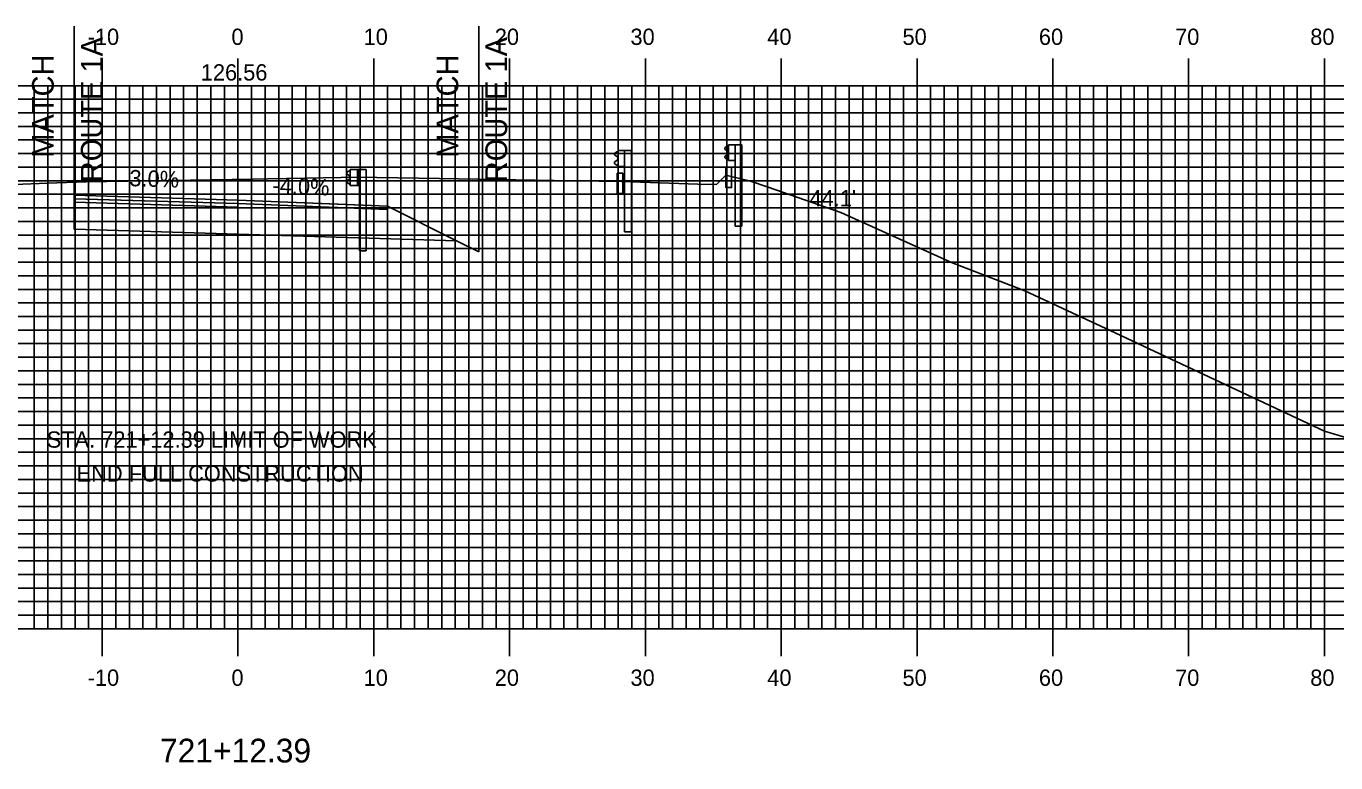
# Model space of a CAD drawing. Extents: x 858445 to 858788, y 364366 to 364586.
# Drawn here: x 858595.3 to 858691.7, y 364433.9 to 364488.2 of the extents above; entities that cross this region are included whole.
import ezdxf

# ---------------------------------------------------------------- set-up
doc = ezdxf.new("R2010")
doc.units = 0
for name, color, linetype in [('ANNOTATION', 7, 'Continuous'), ('D_Guardrail_Beam_Lt', 7, 'Continuous'), ('D_Roadway_Centerline_Text', 7, 'Continuous'), ('D_Roadway_Edge_Shoulder', 7, 'Continuous'), ('D_Roadway_Edge_TW', 7, 'Continuous'), ('D_Roadway_Pavement', 7, 'Continuous'), ('D_Roadway_SlopeLines', 7, 'Continuous'), ('D_Roadway_SubGrade', 7, 'Continuous'), ('D_Text_Standard', 7, 'Continuous'), ('H_V ANNOTATION', 7, 'Continuous'), ('M_Roadway_Centerline', 7, 'Continuous'), ('MAJOR', 7, 'Continuous'), ('MINOR', 7, 'Continuous'), ('S_Curb_Type_1', 7, 'Continuous'), ('S_Guardrail_Beam', 7, 'Continuous'), ('S_Roadway_Centerline', 7, 'Continuous')]:
    doc.layers.add(name, color=color, linetype=linetype)

msp = doc.modelspace()

# ---------------------------------------------------------------- linework, layer by layer
at = {"layer": 'D_Guardrail_Beam_Lt'}
for p, q in [((858619.056, 364477.508), (858618.912, 364477.408)), ((858618.912, 364477.265), (858619.107, 364477.128)), ((858619.107, 364476.929), (858618.912, 364476.793)), ((858619.146, 364477.529), (858619.071, 364477.514)), ((858619.141, 364477.064), (858619.141, 364476.994)), ((858619.146, 364477.612), (858619.833, 364477.612)), ((858619.146, 364476.446), (858619.146, 364477.612)), ((858619.666, 364477.612), (858619.666, 364476.446)), ((858619.771, 364477.612), (858619.771, 364476.446)), ((858619.833, 364477.612), (858620.304, 364477.612)), ((858619.833, 364477.612), (858619.833, 364476.446)), ((858620.304, 364477.612), (858620.304, 364471.612)), ((858618.912, 364476.65), (858619.056, 364476.55)), ((858619.071, 364476.543), (858619.146, 364476.529)), ((858619.833, 364476.446), (858619.146, 364476.446)), ((858619.812, 364471.612), (858619.812, 364476.446)), ((858619.812, 364471.612), (858620.304, 364471.612))]:
    msp.add_line(p, q, dxfattribs=at)
for centre, major_axis, start_param, end_param in [((858618.962, 364477.336), (-0.0877, 0), 5.323254, 7.243116), ((858618.962, 364476.722), (-0.0877, 0), 5.323254, 7.243116), ((858619.079, 364477.474), (-0.0417, 0), 4.907132, 5.323254), ((858619.062, 364477.064), (0.0789, 0), 0, 0.959931), ((858619.062, 364476.994), (0.0789, 0), 5.323254, 6.283185), ((858619.079, 364476.584), (-0.0417, 0), 0.959931, 1.376053)]:
    msp.add_ellipse(centre, major_axis=major_axis, ratio=0.995501, start_param=start_param, end_param=end_param, dxfattribs=at)
at = {"layer": 'D_Roadway_Edge_Shoulder'}
for points in [[(858610.875, 364475.349), (858621.875, 364474.909), (858621.875, 364474.659), (858610.875, 364475.099)], [(858610.875, 364475.349), (858618.875, 364475.029), (858618.875, 364475.029), (858621.875, 364474.909), (858621.875, 364474.659), (858610.875, 364475.099)]]:
    msp.add_lwpolyline(points, close=True, dxfattribs=at)
at = {"layer": 'D_Roadway_Edge_TW'}
for points in [[(858598.817, 364475.711), (858610.875, 364475.349), (858610.875, 364475.099), (858598.817, 364475.461)], [(858598.817, 364475.711), (858610.875, 364475.349), (858610.875, 364475.099), (858598.817, 364475.461)], [(858598.817, 364475.711), (858610.875, 364475.349), (858610.875, 364475.099), (858598.817, 364475.461)], [(858598.817, 364475.711), (858598.817, 364475.711), (858598.817, 364475.461), (858598.817, 364475.461)]]:
    msp.add_lwpolyline(points, close=True, dxfattribs=at)
at = {"layer": 'D_Roadway_Pavement'}
for points in [[(858598.817, 364475.461), (858598.817, 364475.461), (858598.817, 364475.211), (858598.817, 364475.211)], [(858598.839, 364475.46), (858610.875, 364475.099), (858610.875, 364474.849), (858598.839, 364475.21)]]:
    msp.add_lwpolyline(points, close=True, dxfattribs=at)
at = {"layer": 'D_Roadway_SlopeLines'}
msp.add_line((858626.96, 364472.366), (858628.602, 364471.545), dxfattribs=at)
at = {"layer": 'D_Roadway_SubGrade'}
for p, q in [((858598.817, 364488.168), (858598.817, 364473.211)), ((858628.602, 364488.168), (858628.602, 364473.211)), ((858628.602, 364473.211), (858628.602, 364471.545))]:
    msp.add_line(p, q, dxfattribs=at)
for points in [[(858598.817, 364475.211), (858598.817, 364475.211), (858598.817, 364473.211), (858598.817, 364473.211)], [(858598.839, 364475.21), (858610.875, 364474.849), (858610.875, 364472.849), (858598.839, 364473.21)], [(858610.875, 364474.849), (858610.875, 364475.099), (858621.875, 364474.659), (858621.875, 364474.909), (858626.96, 364472.366), (858610.875, 364472.849)]]:
    msp.add_lwpolyline(points, close=True, dxfattribs=at)
at = {"layer": 'MAJOR'}
for p, q in [((858600.875, 364485.791), (858600.875, 364483.787)), ((858610.875, 364485.791), (858610.875, 364483.787)), ((858620.875, 364485.791), (858620.875, 364483.787)), ((858630.875, 364485.791), (858630.875, 364483.787)), ((858640.875, 364485.791), (858640.875, 364483.787)), ((858650.875, 364485.791), (858650.875, 364483.787)), ((858660.875, 364485.791), (858660.875, 364483.787)), ((858670.875, 364485.791), (858670.875, 364483.787)), ((858680.875, 364485.791), (858680.875, 364483.787)), ((858690.875, 364485.791), (858690.875, 364483.787)), ((858470.875, 364483.787), (858750.875, 364483.787)), ((858470.875, 364483.787), (858750.875, 364483.787)), ((858600.875, 364443.787), (858600.875, 364483.787)), ((858610.875, 364443.787), (858610.875, 364483.787)), ((858620.875, 364443.787), (858620.875, 364483.787)), ((858630.875, 364443.787), (858630.875, 364483.787)), ((858640.875, 364443.787), (858640.875, 364483.787)), ((858650.875, 364443.787), (858650.875, 364483.787)), ((858660.875, 364443.787), (858660.875, 364483.787)), ((858670.875, 364443.787), (858670.875, 364483.787)), ((858680.875, 364443.787), (858680.875, 364483.787)), ((858690.875, 364443.787), (858690.875, 364483.787)), ((858470.875, 364478.787), (858750.875, 364478.787)), ((858470.875, 364473.787), (858750.875, 364473.787)), ((858470.875, 364468.787), (858750.875, 364468.787)), ((858470.875, 364463.787), (858750.875, 364463.787)), ((858470.875, 364458.787), (858750.875, 364458.787)), ((858470.875, 364453.787), (858750.875, 364453.787)), ((858470.875, 364448.787), (858750.875, 364448.787)), ((858470.875, 364443.787), (858750.875, 364443.787)), ((858470.875, 364443.787), (858750.875, 364443.787)), ((858600.875, 364441.783), (858600.875, 364443.787)), ((858610.875, 364441.783), (858610.875, 364443.787)), ((858620.875, 364441.783), (858620.875, 364443.787)), ((858630.875, 364441.783), (858630.875, 364443.787)), ((858640.875, 364441.783), (858640.875, 364443.787)), ((858650.875, 364441.783), (858650.875, 364443.787)), ((858660.875, 364441.783), (858660.875, 364443.787)), ((858670.875, 364441.783), (858670.875, 364443.787)), ((858680.875, 364441.783), (858680.875, 364443.787)), ((858690.875, 364441.783), (858690.875, 364443.787))]:
    msp.add_line(p, q, dxfattribs=at)
at = {"layer": 'MINOR'}
for p, q in [((858595.875, 364443.787), (858595.875, 364483.787)), ((858596.875, 364443.787), (858596.875, 364483.787)), ((858597.875, 364443.787), (858597.875, 364483.787)), ((858598.875, 364443.787), (858598.875, 364483.787)), ((858599.875, 364443.787), (858599.875, 364483.787)), ((858601.875, 364443.787), (858601.875, 364483.787)), ((858602.875, 364443.787), (858602.875, 364483.787)), ((858603.875, 364443.787), (858603.875, 364483.787)), ((858604.875, 364443.787), (858604.875, 364483.787)), ((858605.875, 364443.787), (858605.875, 364483.787)), ((858606.875, 364443.787), (858606.875, 364483.787)), ((858607.875, 364443.787), (858607.875, 364483.787)), ((858608.875, 364443.787), (858608.875, 364483.787)), ((858609.875, 364443.787), (858609.875, 364483.787)), ((858611.875, 364443.787), (858611.875, 364483.787)), ((858612.875, 364443.787), (858612.875, 364483.787)), ((858613.875, 364443.787), (858613.875, 364483.787)), ((858614.875, 364443.787), (858614.875, 364483.787)), ((858615.875, 364443.787), (858615.875, 364483.787)), ((858616.875, 364443.787), (858616.875, 364483.787)), ((858617.875, 364443.787), (858617.875, 364483.787)), ((858618.875, 364443.787), (858618.875, 364483.787)), ((858619.875, 364443.787), (858619.875, 364483.787)), ((858621.875, 364443.787), (858621.875, 364483.787)), ((858622.875, 364443.787), (858622.875, 364483.787)), ((858623.875, 364443.787), (858623.875, 364483.787)), ((858624.875, 364443.787), (858624.875, 364483.787)), ((858625.875, 364443.787), (858625.875, 364483.787)), ((858626.875, 364443.787), (858626.875, 364483.787)), ((858627.875, 364443.787), (858627.875, 364483.787)), ((858628.875, 364443.787), (858628.875, 364483.787)), ((858629.875, 364443.787), (858629.875, 364483.787)), ((858631.875, 364443.787), (858631.875, 364483.787)), ((858632.875, 364443.787), (858632.875, 364483.787)), ((858633.875, 364443.787), (858633.875, 364483.787)), ((858634.875, 364443.787), (858634.875, 364483.787)), ((858635.875, 364443.787), (858635.875, 364483.787)), ((858636.875, 364443.787), (858636.875, 364483.787)), ((858637.875, 364443.787), (858637.875, 364483.787)), ((858638.875, 364443.787), (858638.875, 364483.787)), ((858639.875, 364443.787), (858639.875, 364483.787)), ((858641.875, 364443.787), (858641.875, 364483.787)), ((858642.875, 364443.787), (858642.875, 364483.787)), ((858643.875, 364443.787), (858643.875, 364483.787)), ((858644.875, 364443.787), (858644.875, 364483.787)), ((858645.875, 364443.787), (858645.875, 364483.787)), ((858646.875, 364443.787), (858646.875, 364483.787)), ((858647.875, 364443.787), (858647.875, 364483.787)), ((858648.875, 364443.787), (858648.875, 364483.787)), ((858649.875, 364443.787), (858649.875, 364483.787)), ((858651.875, 364443.787), (858651.875, 364483.787)), ((858652.875, 364443.787), (858652.875, 364483.787)), ((858653.875, 364443.787), (858653.875, 364483.787)), ((858654.875, 364443.787), (858654.875, 364483.787)), ((858655.875, 364443.787), (858655.875, 364483.787)), ((858656.875, 364443.787), (858656.875, 364483.787)), ((858657.875, 364443.787), (858657.875, 364483.787)), ((858658.875, 364443.787), (858658.875, 364483.787)), ((858659.875, 364443.787), (858659.875, 364483.787)), ((858661.875, 364443.787), (858661.875, 364483.787)), ((858662.875, 364443.787), (858662.875, 364483.787)), ((858663.875, 364443.787), (858663.875, 364483.787)), ((858664.875, 364443.787), (858664.875, 364483.787)), ((858665.875, 364443.787), (858665.875, 364483.787)), ((858666.875, 364443.787), (858666.875, 364483.787)), ((858667.875, 364443.787), (858667.875, 364483.787)), ((858668.875, 364443.787), (858668.875, 364483.787)), ((858669.875, 364443.787), (858669.875, 364483.787)), ((858671.875, 364443.787), (858671.875, 364483.787)), ((858672.875, 364443.787), (858672.875, 364483.787)), ((858673.875, 364443.787), (858673.875, 364483.787)), ((858674.875, 364443.787), (858674.875, 364483.787)), ((858675.875, 364443.787), (858675.875, 364483.787)), ((858676.875, 364443.787), (858676.875, 364483.787)), ((858677.875, 364443.787), (858677.875, 364483.787)), ((858678.875, 364443.787), (858678.875, 364483.787)), ((858679.875, 364443.787), (858679.875, 364483.787)), ((858681.875, 364443.787), (858681.875, 364483.787)), ((858682.875, 364443.787), (858682.875, 364483.787)), ((858683.875, 364443.787), (858683.875, 364483.787)), ((858684.875, 364443.787), (858684.875, 364483.787)), ((858685.875, 364443.787), (858685.875, 364483.787)), ((858686.875, 364443.787), (858686.875, 364483.787)), ((858687.875, 364443.787), (858687.875, 364483.787)), ((858688.875, 364443.787), (858688.875, 364483.787)), ((858689.875, 364443.787), (858689.875, 364483.787)), ((858470.875, 364482.787), (858750.875, 364482.787)), ((858470.875, 364481.787), (858750.875, 364481.787)), ((858470.875, 364480.787), (858750.875, 364480.787)), ((858470.875, 364479.787), (858750.875, 364479.787)), ((858470.875, 364477.787), (858750.875, 364477.787)), ((858470.875, 364476.787), (858750.875, 364476.787)), ((858470.875, 364475.787), (858750.875, 364475.787)), ((858470.875, 364474.787), (858750.875, 364474.787)), ((858470.875, 364472.787), (858750.875, 364472.787)), ((858470.875, 364471.787), (858750.875, 364471.787)), ((858470.875, 364470.787), (858750.875, 364470.787)), ((858470.875, 364469.787), (858750.875, 364469.787)), ((858470.875, 364467.787), (858750.875, 364467.787)), ((858470.875, 364466.787), (858750.875, 364466.787)), ((858470.875, 364465.787), (858750.875, 364465.787)), ((858470.875, 364464.787), (858750.875, 364464.787)), ((858470.875, 364462.787), (858750.875, 364462.787)), ((858470.875, 364461.787), (858750.875, 364461.787)), ((858470.875, 364460.787), (858750.875, 364460.787)), ((858470.875, 364459.787), (858750.875, 364459.787)), ((858470.875, 364457.787), (858750.875, 364457.787)), ((858470.875, 364456.787), (858750.875, 364456.787)), ((858470.875, 364455.787), (858750.875, 364455.787)), ((858470.875, 364454.787), (858750.875, 364454.787)), ((858470.875, 364452.787), (858750.875, 364452.787)), ((858470.875, 364451.787), (858750.875, 364451.787)), ((858470.875, 364450.787), (858750.875, 364450.787)), ((858470.875, 364449.787), (858750.875, 364449.787)), ((858470.875, 364447.787), (858750.875, 364447.787)), ((858470.875, 364446.787), (858750.875, 364446.787)), ((858470.875, 364445.787), (858750.875, 364445.787)), ((858470.875, 364444.787), (858750.875, 364444.787))]:
    msp.add_line(p, q, dxfattribs=at)
at = {"layer": 'S_Curb_Type_1'}
for points in [[(858646.805, 364477.776), (858647.221, 364477.776), (858647.221, 364476.276), (858646.805, 364476.276)], [(858646.805, 364477.776), (858647.221, 364477.776), (858647.221, 364476.276), (858646.805, 364476.276)], [(858638.794, 364477.343), (858639.211, 364477.343), (858639.211, 364475.843), (858638.794, 364475.843)]]:
    msp.add_lwpolyline(points, close=True, dxfattribs=at)
at = {"layer": 'S_Guardrail_Beam'}
for p, q in [((858638.759, 364478.918), (858638.616, 364478.818)), ((858638.858, 364478.939), (858638.776, 364478.925)), ((858638.858, 364479.012), (858639.347, 364479.012)), ((858638.858, 364477.846), (858638.858, 364479.012)), ((858639.347, 364479.012), (858639.839, 364479.012)), ((858639.347, 364479.012), (858639.347, 364477.846)), ((858639.839, 364479.012), (858639.839, 364473.012)), ((858646.899, 364479.34), (858646.755, 364479.24)), ((858646.899, 364479.34), (858646.755, 364479.24)), ((858646.755, 364479.097), (858646.951, 364478.961)), ((858646.755, 364479.097), (858646.951, 364478.961)), ((858646.951, 364478.741), (858646.755, 364478.605)), ((858646.951, 364478.741), (858646.755, 364478.605)), ((858646.997, 364479.362), (858646.915, 364479.347)), ((858646.997, 364479.362), (858646.915, 364479.347)), ((858646.984, 364478.897), (858646.984, 364478.806)), ((858646.984, 364478.897), (858646.984, 364478.806)), ((858646.997, 364479.435), (858647.487, 364479.435)), ((858646.997, 364478.268), (858646.997, 364479.435)), ((858646.997, 364479.435), (858647.487, 364479.435)), ((858646.997, 364478.268), (858646.997, 364479.435)), ((858647.487, 364479.435), (858647.979, 364479.435)), ((858647.487, 364479.435), (858647.487, 364478.268)), ((858647.487, 364479.435), (858647.979, 364479.435)), ((858647.487, 364479.435), (858647.487, 364478.268)), ((858647.979, 364479.435), (858647.979, 364473.435)), ((858647.979, 364479.435), (858647.979, 364473.435)), ((858638.616, 364478.675), (858638.811, 364478.539)), ((858638.811, 364478.319), (858638.616, 364478.183)), ((858638.616, 364478.04), (858638.759, 364477.94)), ((858638.776, 364477.933), (858638.858, 364477.919)), ((858638.845, 364478.475), (858638.845, 364478.384)), ((858639.347, 364477.846), (858638.858, 364477.846)), ((858639.347, 364473.012), (858639.347, 364477.846)), ((858646.755, 364478.462), (858646.899, 364478.362)), ((858646.755, 364478.462), (858646.899, 364478.362)), ((858646.915, 364478.355), (858646.997, 364478.341)), ((858646.915, 364478.355), (858646.997, 364478.341)), ((858647.487, 364478.268), (858646.997, 364478.268)), ((858647.487, 364478.268), (858646.997, 364478.268)), ((858647.487, 364473.435), (858647.487, 364478.268)), ((858647.487, 364473.435), (858647.487, 364478.268)), ((858639.347, 364473.012), (858639.839, 364473.012)), ((858647.487, 364473.435), (858647.979, 364473.435)), ((858647.487, 364473.435), (858647.979, 364473.435))]:
    msp.add_line(p, q, dxfattribs=at)
for centre, major_axis, start_param, end_param in [((858638.666, 364478.747), (-0.0877, 0), 5.323254, 7.243116), ((858638.783, 364478.884), (-0.0417, 0), 4.886922, 5.323254), ((858646.806, 364479.169), (-0.0877, 0), 5.323254, 7.243116), ((858646.806, 364479.169), (-0.0877, 0), 5.323254, 7.243116), ((858646.923, 364479.306), (-0.0417, 0), 4.886922, 5.323254), ((858646.923, 364479.306), (-0.0417, 0), 4.886922, 5.323254), ((858646.905, 364478.897), (0.0789, 0), 0, 0.959931), ((858646.905, 364478.897), (0.0789, 0), 0, 0.959931), ((858646.905, 364478.806), (0.0789, 0), 5.323254, 6.283185), ((858646.905, 364478.806), (0.0789, 0), 5.323254, 6.283185), ((858638.666, 364478.111), (-0.0877, 0), 5.323254, 7.243116), ((858638.783, 364477.974), (-0.0417, 0), 0.959931, 1.396263), ((858638.766, 364478.475), (0.0789, 0), 0, 0.959931), ((858638.766, 364478.384), (0.0789, 0), 5.323254, 6.283185), ((858646.806, 364478.534), (-0.0877, 0), 5.323254, 7.243116), ((858646.806, 364478.534), (-0.0877, 0), 5.323254, 7.243116), ((858646.923, 364478.396), (-0.0417, 0), 0.959931, 1.396263), ((858646.923, 364478.396), (-0.0417, 0), 0.959931, 1.396263)]:
    msp.add_ellipse(centre, major_axis=major_axis, ratio=0.995501, start_param=start_param, end_param=end_param, dxfattribs=at)
at = {"layer": 'S_Roadway_Centerline'}
msp.add_lwpolyline([(858592.042, 364476.413), (858596.835, 364476.612), (858599.692, 364476.712), (858611.96, 364476.903), (858613.084, 364476.918), (858615.809, 364476.972), (858619.82, 364477.047), (858621.11, 364477.033), (858625.712, 364476.955), (858634.153, 364476.805), (858639.108, 364476.718), (858644.74, 364476.537), (858646.121, 364476.51), (858646.672, 364477.077), (858646.805, 364477.193), (858647.083, 364477.125), (858648.618, 364476.754), (858649.904, 364476.315), (858655.27, 364474.458), (858663.406, 364470.771), (858668.821, 364468.678), (858675.089, 364465.755), (858690.872, 364458.351), (858702.378, 364454.899)], dxfattribs=at)

# ---------------------------------------------------------------- texts
at = {"layer": 'ANNOTATION'}
for s, height, rotation, p in [('ROUTE 1A', 1.6, 90, (858600.909, 364476.672)), ('ROUTE 1A', 1.6, 90, (858630.694, 364476.672)), ('MATCH', 1.6, 90, (858597.309, 364478.478)), ('MATCH', 1.6, 90, (858627.094, 364478.478)), ('3.0%', 1.2, 358.28156, (858602.863, 364476.39)), ('-4.0%', 1.2, 357.70939, (858613.398, 364475.859))]:
    msp.add_text(s, height=height, rotation=rotation, dxfattribs=at).set_placement(p)
at = {"layer": 'D_Roadway_Centerline_Text'}
msp.add_text('126.56', height=1.2, dxfattribs=at).set_placement((858608.135, 364484.166))
at = {"layer": 'D_Text_Standard'}
for s, p in [("44.1'", (858652.959, 364474.901)), ('STA. 721+12.39 LIMIT OF WORK', (858596.794, 364457.126)), ('END FULL CONSTRUCTION', (858598.996, 364454.626))]:
    msp.add_text(s, height=1.2, dxfattribs=at).set_placement(p)
at = {"layer": 'H_V ANNOTATION'}
for s, height, p in [('-10', 1.2, (858599.804, 364486.787)), ('0', 1.2, (858610.393, 364486.787)), ('10', 1.2, (858620.125, 364486.787)), ('20', 1.2, (858629.783, 364486.787)), ('30', 1.2, (858639.772, 364486.787)), ('40', 1.2, (858649.847, 364486.787)), ('50', 1.2, (858659.804, 364486.787)), ('60', 1.2, (858669.847, 364486.787)), ('70', 1.2, (858679.879, 364486.787)), ('80', 1.2, (858689.826, 364486.787)), ('-10', 1.2, (858599.804, 364439.587)), ('0', 1.2, (858610.393, 364439.587)), ('10', 1.2, (858620.125, 364439.587)), ('20', 1.2, (858629.783, 364439.587)), ('30', 1.2, (858639.772, 364439.587)), ('40', 1.2, (858649.847, 364439.587)), ('50', 1.2, (858659.804, 364439.587)), ('60', 1.2, (858669.847, 364439.587)), ('70', 1.2, (858679.879, 364439.587)), ('80', 1.2, (858689.826, 364439.587)), ('721+12.39', 1.75, (858605.132, 364433.943))]:
    msp.add_text(s, height=height, dxfattribs=at).set_placement(p)
at = {"layer": 'M_Roadway_Centerline'}
for s, p in [('C', (858619.73, 364477.098)), ('L', (858619.736, 364477.091)), ('C', (858611.733, 364476.676)), ('L', (858611.738, 364476.669))]:
    msp.add_text(s, height=0.0146, dxfattribs=at).set_placement(p)

doc.saveas('drawing.dxf')
